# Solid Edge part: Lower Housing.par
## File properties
Author: CADCIM
Template: NORMENG.PAR
Last saved by: MYPC
Revision: 5
Application: Solid Edge
Density: 0 lbm/in^3
Accuracy: 0.99
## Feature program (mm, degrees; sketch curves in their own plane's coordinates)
sketch for "unnamed Protrusion 1" plane through (0, 0, 0) normal (0, -1, 0) x-axis (1, 0, 0)
  line (0, 0) -> (-190.5, 0)
  line (-190.5, 0) -> (-190.5, -10.414)
  line (-190.5, -10.414) -> (-152.4, -10.414)
  arc centre (-0.1761, -3.0894) radius 152.4 from (-88.9, -127) to (-152.4, -10.414) cw
  line (-88.9, -127) -> (-177.8, -127)
  line (-177.8, -127) -> (-177.8, -165.1)
  line (-177.8, -165.1) -> (0, -165.1)
  line (177.8, -165.1) -> (0, -165.1)
  line (177.8, -127) -> (177.8, -165.1)
  line (88.9, -127) -> (177.8, -127)
  arc centre (0.1761, -3.0894) radius 152.4 from (88.9, -127) to (152.4, -10.414) ccw
  line (190.5, -10.414) -> (152.4, -10.414)
  line (190.5, 0) -> (190.5, -10.414)
  line (0, 0) -> (190.5, 0)
extrude "unnamed Protrusion 1" add finite 203.2 symmetric
sketch for "RevolvedCutout_1" plane through (0, 0, 0) normal (0, 0, 1) x-axis (0, 1, 0)
  line (-95.25, 0) -> (95.25, 0)
  line (95.25, 0) -> (95.25, 146.05)
  line (95.25, 146.05) -> (-95.25, 146.05)
  line (-95.25, 146.05) -> (-95.25, 0)
  dimension (linear) = 95.25
revolve "RevolvedCutout_1" cut finite 180 deg
sketch for "unnamed Cutout 1" plane through (0, -101.6, -82.55) normal (0, -1, 0) x-axis (1, 0, 0)
  arc centre (0, 82.55) radius 123.825 from (123.825, 82.55) to (-123.825, 82.55) cw
  line (-123.825, 82.55) -> (123.825, 82.55)
extrude "unnamed Cutout 1" cut through along -normal
sketch for "unnamed Cutout 2" plane through (0, 101.6, -82.55) normal (0, 1, 0) x-axis (-1, 0, 0)
  arc centre (0, 82.55) radius 38.1 from (38.1, 82.55) to (-38.1, 82.55) cw
  line (-38.1, 82.55) -> (38.1, 82.55)
extrude "unnamed Cutout 2" cut through along -normal
sketch for "Hole_1" plane through (114.3, 0, 0) normal (0, 0, 1) x-axis (0, 1, 0)
  hole centre (-76.2, -57.15) bore radius 5.207
hole "Hole_1" diameter 10.414 through
pattern "unnamed Pattern 1" of "Hole_1"
pattern "unnamed Pattern 2"
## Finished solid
Body 1: solid body, 28 faces, 70 edges, 36 vertices.
  Faces by surface: plane 15, cylinder 13
  Edges by curve: line 44, circle 26
Bounding box of the edges (mm): 381.000 x 203.200 x 165.100, from (-190.5, -101.6, -165.1) to (190.5, 101.6, 0).
Cylindrical faces by radius (mm): R5.207 x8, R38.1 x1, R123.825 x1, R146.05 x1, R152.4 x2
Planar faces by outward normal: +x 2, +y 2, +z 4, -x 2, -y 2, -z 3
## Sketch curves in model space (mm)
line (190.5, 0, 0) -> (190.5, 0, -10.414)
line (190.5, 0, -10.414) -> (152.4, 0, -10.414)
arc centre (0.1761, 0, -3.0894) radius 152.4 from (88.9, 0, -127) through (134.012, 0, -75.9848) to (152.4, 0, -10.414)
line (88.9, 0, -127) -> (177.8, 0, -127)
line (177.8, 0, -127) -> (177.8, 0, -165.1)
line (177.8, 0, -165.1) -> (0, 0, -165.1)
line (-177.8, 0, -165.1) -> (0, 0, -165.1)
line (-177.8, 0, -127) -> (-177.8, 0, -165.1)
line (-88.9, 0, -127) -> (-177.8, 0, -127)
arc centre (-0.1761, 0, -3.0894) radius 152.4 from (-88.9, 0, -127) through (-134.012, 0, -75.9848) to (-152.4, 0, -10.414)
line (-190.5, 0, -10.414) -> (-152.4, 0, -10.414)
line (-190.5, 0, 0) -> (-190.5, 0, -10.414)
line (0, 0, 0) -> (-190.5, 0, 0)
line (0, 0, 0) -> (190.5, 0, 0)
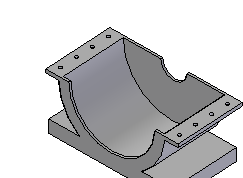
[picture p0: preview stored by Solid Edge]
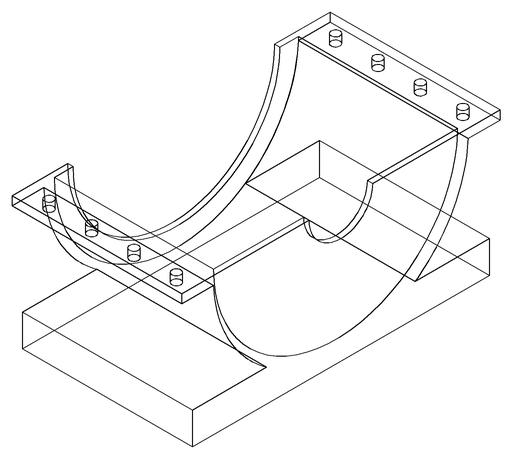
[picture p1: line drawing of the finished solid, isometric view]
